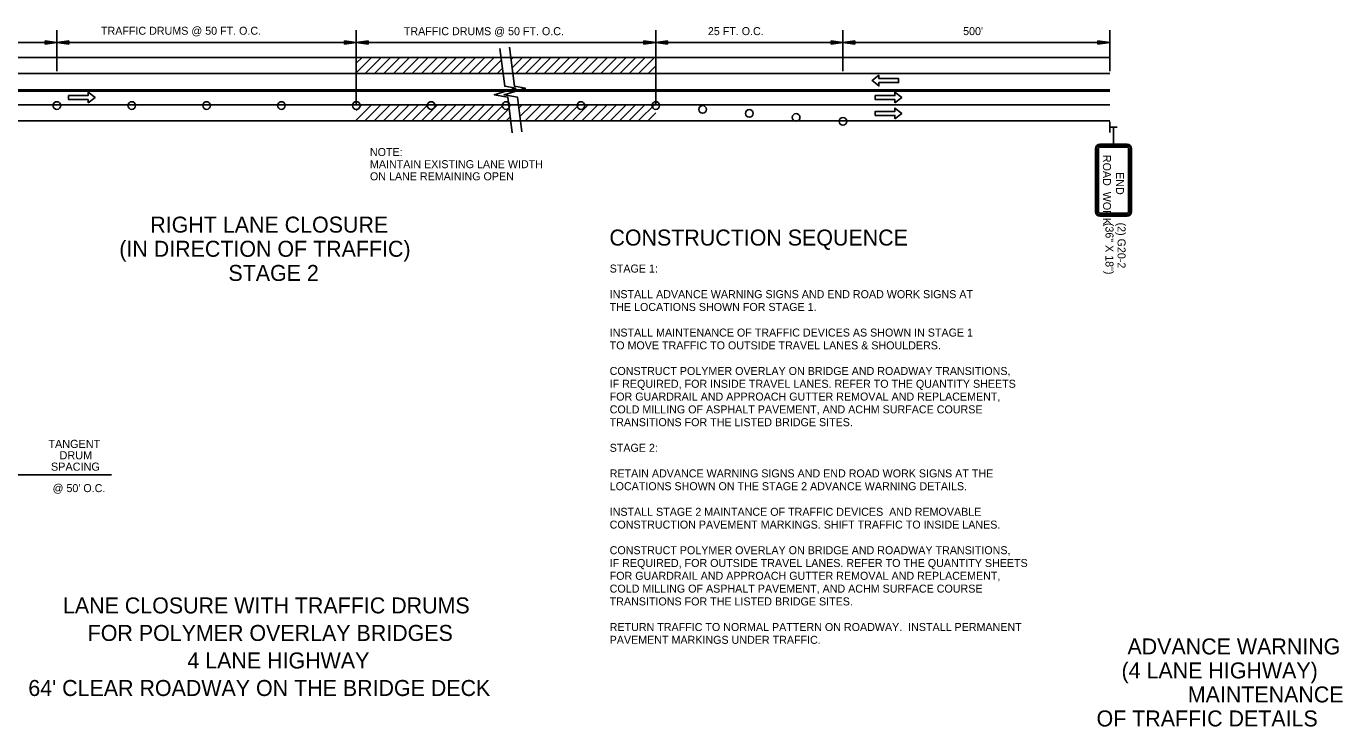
# Model space of a CAD drawing. Extents: x 1930579 to 1937984, y 596452 to 597630.
# Drawn here: x 1936993 to 1937980, y 596607 to 597132 of the extents above; entities that cross this region are included whole.
import ezdxf

# ---------------------------------------------------------------- set-up
doc = ezdxf.new("R2010")
doc.units = 0
for name, color, linetype in [('Default', 7, 'Continuous'), ('P_TC_Signs_Temporary', 7, 'Continuous'), ('R_Annotation', 7, 'Continuous'), ('R_Striping', 7, 'Continuous')]:
    doc.layers.add(name, color=color, linetype=linetype)

msp = doc.modelspace()

# ---------------------------------------------------------------- linework, layer by layer
at = {"layer": 'Default'}
for p, q in [((1937015.53, 597119.89), (1937006.66, 597121.22)), ((1937006.66, 597121.22), (1937006.66, 597118.56)), ((1937015.53, 597129.19), (1937015.53, 597098.47)), ((1937015.53, 597119.89), (1937024.4, 597121.22)), ((1937024.4, 597121.22), (1937024.4, 597118.56)), ((1937231.17, 597118.56), (1937231.17, 597121.22)), ((1937231.17, 597121.22), (1937240.04, 597119.89)), ((1937240.04, 597129.19), (1937240.04, 597073.09)), ((1937248.9, 597121.22), (1937240.04, 597119.89)), ((1937248.9, 597118.56), (1937248.9, 597121.22)), ((1937455.68, 597118.56), (1937455.68, 597121.22)), ((1937455.68, 597121.22), (1937464.54, 597119.89)), ((1937464.54, 597129.19), (1937464.54, 597073.09)), ((1937473.41, 597121.22), (1937464.54, 597119.89)), ((1937473.41, 597118.56), (1937473.41, 597121.22)), ((1937595.99, 597118.56), (1937595.99, 597121.22)), ((1937595.99, 597121.22), (1937604.86, 597119.89)), ((1937604.86, 597129.19), (1937604.86, 597098.47)), ((1937613.73, 597121.22), (1937604.86, 597119.89)), ((1937613.73, 597118.56), (1937613.73, 597121.22)), ((1937795.99, 597118.56), (1937795.99, 597121.22)), ((1937795.99, 597121.22), (1937804.86, 597119.89)), ((1937804.86, 597129.19), (1937804.86, 597098.47)), ((1937015.53, 597119.89), (1936791.02, 597119.89)), ((1937006.66, 597118.56), (1937015.53, 597119.89)), ((1937240.04, 597119.89), (1937015.53, 597119.89)), ((1937024.4, 597118.56), (1937015.53, 597119.89)), ((1937240.04, 597119.89), (1937231.17, 597118.56)), ((1937464.54, 597119.89), (1937240.04, 597119.89)), ((1937240.04, 597119.89), (1937248.9, 597118.56)), ((1937464.54, 597119.89), (1937455.68, 597118.56)), ((1937604.86, 597119.89), (1937464.54, 597119.89)), ((1937464.54, 597119.89), (1937473.41, 597118.56)), ((1937604.86, 597119.89), (1937595.99, 597118.56)), ((1937804.86, 597119.89), (1937604.86, 597119.89)), ((1937604.86, 597119.89), (1937613.73, 597118.56)), ((1937804.86, 597119.89), (1937795.99, 597118.56)), ((1937804.86, 597108.65), (1936452.69, 597108.65)), ((1937240.04, 597097.16), (1937251.53, 597108.65)), ((1937240.04, 597104.23), (1937244.46, 597108.65)), ((1937246.6, 597096.65), (1937258.6, 597108.65)), ((1937253.67, 597096.65), (1937265.67, 597108.65)), ((1937260.74, 597096.65), (1937272.74, 597108.65)), ((1937267.81, 597096.65), (1937279.81, 597108.65)), ((1937274.88, 597096.65), (1937286.88, 597108.65)), ((1937281.95, 597096.65), (1937293.95, 597108.65)), ((1937289.02, 597096.65), (1937301.02, 597108.65)), ((1937296.09, 597096.65), (1937308.09, 597108.65)), ((1937303.17, 597096.65), (1937315.17, 597108.65)), ((1937310.24, 597096.65), (1937322.24, 597108.65)), ((1937317.31, 597096.65), (1937329.31, 597108.65)), ((1937324.38, 597096.65), (1937336.38, 597108.65)), ((1937331.45, 597096.65), (1937343.45, 597108.65)), ((1937338.52, 597096.65), (1937348.79, 597106.92)), ((1937356.05, 597107.11), (1937357.59, 597108.65)), ((1937356.84, 597100.83), (1937364.66, 597108.65)), ((1937359.73, 597096.65), (1937371.73, 597108.65)), ((1937366.81, 597096.65), (1937378.81, 597108.65)), ((1937373.88, 597096.65), (1937385.88, 597108.65)), ((1937380.95, 597096.65), (1937392.95, 597108.65)), ((1937388.02, 597096.65), (1937400.02, 597108.65)), ((1937395.09, 597096.65), (1937407.09, 597108.65)), ((1937402.16, 597096.65), (1937414.16, 597108.65)), ((1937409.23, 597096.65), (1937421.23, 597108.65)), ((1937416.3, 597096.65), (1937428.3, 597108.65)), ((1937423.37, 597096.65), (1937435.37, 597108.65)), ((1937430.45, 597096.65), (1937442.45, 597108.65)), ((1937437.52, 597096.65), (1937449.52, 597108.65)), ((1937444.59, 597096.65), (1937456.59, 597108.65)), ((1937451.66, 597096.65), (1937463.66, 597108.65)), ((1937458.73, 597096.65), (1937464.54, 597102.47)), ((1937804.86, 597096.65), (1936452.69, 597096.65)), ((1937345.59, 597096.65), (1937349.58, 597100.64)), ((1937804.86, 597084.42), (1936452.69, 597084.42)), ((1937804.86, 597083.27), (1936452.69, 597083.27)), ((1937804.86, 597073.09), (1936452.69, 597073.09)), ((1937239.31, 597061.09), (1937251.31, 597073.09)), ((1937240.04, 597068.88), (1937244.24, 597073.09)), ((1937246.39, 597061.09), (1937258.39, 597073.09)), ((1937253.46, 597061.09), (1937265.46, 597073.09)), ((1937260.53, 597061.09), (1937272.53, 597073.09)), ((1937267.6, 597061.09), (1937279.6, 597073.09)), ((1937274.67, 597061.09), (1937286.67, 597073.09)), ((1937281.74, 597061.09), (1937293.74, 597073.09)), ((1937288.81, 597061.09), (1937300.81, 597073.09)), ((1937295.88, 597061.09), (1937307.88, 597073.09)), ((1937302.95, 597061.09), (1937314.95, 597073.09)), ((1937310.03, 597061.09), (1937322.03, 597073.09)), ((1937317.1, 597061.09), (1937329.1, 597073.09)), ((1937324.17, 597061.09), (1937336.17, 597073.09)), ((1937331.24, 597061.09), (1937343.24, 597073.09)), ((1937338.31, 597061.09), (1937350.31, 597073.09)), ((1937350.85, 597080.7), (1937350.89, 597080.74)), ((1937361.97, 597070.61), (1937364.45, 597073.09)), ((1937362.73, 597064.29), (1937371.52, 597073.09)), ((1937366.59, 597061.09), (1937378.59, 597073.09)), ((1937373.67, 597061.09), (1937385.67, 597073.09)), ((1937380.74, 597061.09), (1937392.74, 597073.09)), ((1937387.81, 597061.09), (1937399.81, 597073.09)), ((1937394.88, 597061.09), (1937406.88, 597073.09)), ((1937401.95, 597061.09), (1937413.95, 597073.09)), ((1937409.02, 597061.09), (1937421.02, 597073.09)), ((1937416.09, 597061.09), (1937428.09, 597073.09)), ((1937423.16, 597061.09), (1937435.16, 597073.09)), ((1937430.23, 597061.09), (1937442.23, 597073.09)), ((1937437.3, 597061.09), (1937449.3, 597073.09)), ((1937444.38, 597061.09), (1937456.38, 597073.09)), ((1937451.45, 597061.09), (1937464.54, 597074.18)), ((1937463.45, 597073.09), (1937464.54, 597074.18)), ((1937345.38, 597061.09), (1937354.71, 597070.42)), ((1937352.45, 597061.09), (1937355.47, 597064.1)), ((1937458.52, 597061.09), (1937464.54, 597067.11)), ((1937804.86, 597061.09), (1936452.69, 597061.09)), ((1937804.86, 597052.43), (1937804.86, 597060.41)), ((1937804.98, 597056.4), (1937810.42, 597056.4))]:
    msp.add_line(p, q, dxfattribs=at)
for points in [[(1937347.74, 597115.35), (1937351.28, 597087.03), (1937359.53, 597085.57), (1937343.51, 597080.71), (1937353.71, 597078.77), (1937356.93, 597052)], [(1937354.91, 597116.24), (1937358.56, 597087.03), (1937366.82, 597085.57), (1937350.79, 597080.71), (1937360.99, 597078.77), (1937364.11, 597052.86)]]:
    msp.add_lwpolyline(points, dxfattribs=at)
for centre in [(1937015.53, 597072.6), (1937071.66, 597072.6), (1937127.78, 597072.6), (1937183.91, 597072.6), (1937240.04, 597072.6), (1937296.16, 597072.6), (1937352.29, 597072.6), (1937408.42, 597072.6), (1937464.54, 597072.6), (1937499.62, 597069.63), (1937534.7, 597066.66), (1937569.78, 597063.68), (1937604.86, 597060.71)]:
    msp.add_circle(centre, 2.87, dxfattribs=at)
at = {"layer": 'P_TC_Signs_Temporary'}
for p, q in [((1937817.83, 597043.6), (1937797.58, 597043.6)), ((1937817.83, 597042.66), (1937797.58, 597042.66)), ((1937794.2, 597040.22), (1937794.2, 596992.97)), ((1937795.14, 597040.22), (1937795.14, 596992.97)), ((1937796.45, 597040.22), (1937796.45, 596992.97)), ((1937817.83, 597041.35), (1937797.58, 597041.35)), ((1937818.95, 596992.97), (1937818.95, 597040.22)), ((1937820.26, 596992.97), (1937820.26, 597040.22)), ((1937821.2, 596992.97), (1937821.2, 597040.22)), ((1937797.58, 596991.85), (1937817.83, 596991.85)), ((1937797.58, 596990.54), (1937817.83, 596990.54)), ((1937797.58, 596989.6), (1937817.83, 596989.6))]:
    msp.add_line(p, q, dxfattribs=at)
for centre, radius, start, end in [((1937797.58, 597040.22), 3.38, 90, 180), ((1937797.58, 597040.22), 2.44, 90, 180), ((1937817.83, 597040.22), 3.37, 360, 90), ((1937817.83, 597040.22), 2.44, 360, 90), ((1937797.58, 597040.22), 1.13, 90, 180), ((1937817.83, 597040.22), 1.13, 360, 90), ((1937797.58, 596992.97), 3.37, 180, 270), ((1937797.58, 596992.97), 2.44, 180, 270), ((1937797.58, 596992.97), 1.13, 180, 270), ((1937817.83, 596992.97), 2.44, 270, 360), ((1937817.83, 596992.97), 1.13, 270, 360), ((1937817.83, 596992.97), 3.38, 270, 360)]:
    msp.add_arc(centre, radius, start, end, dxfattribs=at)
at = {"layer": 'R_Annotation'}
for p, q in [((1937807.7, 597056.4), (1937807.7, 597043.6)), ((1936487.9, 596795.58), (1937056.56, 596795.58))]:
    msp.add_line(p, q, dxfattribs=at)
at = {"layer": 'R_Striping'}
for points in [[(1937631.9, 597095.24), (1937626.7, 597091.24), (1937631.9, 597087.24), (1937631.9, 597089.74), (1937646.61, 597089.74), (1937646.61, 597092.74), (1937631.9, 597092.74)], [(1937038.98, 597074.5), (1937044.17, 597078.5), (1937038.98, 597082.5), (1937038.98, 597080), (1937024.27, 597080), (1937024.27, 597077), (1937038.98, 597077)], [(1937643.82, 597074.5), (1937649.01, 597078.5), (1937643.82, 597082.5), (1937643.82, 597080), (1937629.11, 597080), (1937629.11, 597077), (1937643.82, 597077)], [(1937643.82, 597062.73), (1937649.01, 597066.73), (1937643.82, 597070.73), (1937643.82, 597068.23), (1937629.11, 597068.23), (1937629.11, 597065.23), (1937643.82, 597065.23)]]:
    msp.add_lwpolyline(points, close=True, dxfattribs=at)

# ---------------------------------------------------------------- texts
at = {"layer": 'Default'}
for s, height, p in [('TRAFFIC DRUMS @ 50 FT. O.C.', 6, (1937048.61, 597125.66)), ('TRAFFIC DRUMS @ 50 FT. O.C.', 6, (1937275.67, 597125.33)), ('25 FT. O.C.', 6, (1937503.59, 597125.38)), ("500'", 6, (1937694.96, 597125.38)), ('RIGHT LANE CLOSURE', 12, (1937085.58, 596977.28)), ('(IN DIRECTION OF TRAFFIC)', 12, (1937062.33, 596959.17)), ('STAGE 2', 12, (1937144.16, 596941.05)), ('LANE CLOSURE WITH TRAFFIC DRUMS', 12, (1937020.12, 596691.73)), ('FOR POLYMER OVERLAY BRIDGES', 12, (1937038.64, 596671.09)), ('4 LANE HIGHWAY', 12, (1937113.38, 596650.45)), ("64' CLEAR ROADWAY ON THE BRIDGE DECK", 12, (1936994.13, 596629.81))]:
    msp.add_text(s, height=height, rotation=360, dxfattribs=at).set_placement(p)
at = {"layer": 'P_TC_Signs_Temporary'}
for s, p in [('ROAD  WORK', (1937799.83, 597035.56)), ('END', (1937809.58, 597022.63))]:
    msp.add_text(s, height=6, rotation=270, dxfattribs=at).set_placement(p)
at = {"layer": 'R_Annotation'}
for s, height, rotation, p in [('NOTE:', 6, 360, (1937250.26, 597034.72)), ('ON LANE REMAINING OPEN', 6, 360, (1937250.26, 597016.5)), ('MAINTAIN EXISTING LANE WIDTH', 6, 360, (1937250.26, 597025.61)), ('(36" X 18")', 6, 270, (1937801.7, 596984.6)), ('(2) G20-2', 6, 270, (1937810.76, 596984.81)), ('CONSTRUCTION SEQUENCE', 12, 360, (1937429.8, 596967.58)), ('STAGE 1:', 6, 360, (1937429.99, 596947.33)), ('INSTALL ADVANCE WARNING SIGNS AND END ROAD WORK SIGNS AT', 6, 360, (1937429.99, 596928.13)), ('THE LOCATIONS SHOWN FOR STAGE 1.', 6, 360, (1937429.99, 596918.53)), ('INSTALL MAINTENANCE OF TRAFFIC DEVICES AS SHOWN IN STAGE 1', 6, 360, (1937429.99, 596899.33)), ('TO MOVE TRAFFIC TO OUTSIDE TRAVEL LANES & SHOULDERS.', 6, 360, (1937429.99, 596889.73)), ('CONSTRUCT POLYMER OVERLAY ON BRIDGE AND ROADWAY TRANSITIONS,', 6, 360, (1937429.99, 596870.53)), ('IF REQUIRED, FOR INSIDE TRAVEL LANES. REFER TO THE QUANTITY SHEETS ', 6, 360, (1937429.99, 596860.93)), ('FOR GUARDRAIL AND APPROACH GUTTER REMOVAL AND REPLACEMENT, ', 6, 360, (1937429.99, 596851.33)), ('COLD MILLING OF ASPHALT PAVEMENT, AND ACHM SURFACE COURSE ', 6, 360, (1937429.99, 596841.73)), ('TRANSITIONS FOR THE LISTED BRIDGE SITES.', 6, 360, (1937429.99, 596832.13)), ('TANGENT', 6.094, 360, (1937009.17, 596815.8)), ('STAGE 2:', 6, 360, (1937429.99, 596812.93)), ('DRUM', 6.094, 360, (1937017.54, 596807.27)), ('SPACING', 6.094, 360, (1937011.09, 596798.74)), ('RETAIN ADVANCE WARNING SIGNS AND END ROAD WORK SIGNS AT THE', 6, 360, (1937429.99, 596793.73)), ("@ 50' O.C.", 6, 360, (1937012.34, 596782.7)), ('LOCATIONS SHOWN ON THE STAGE 2 ADVANCE WARNING DETAILS.', 6, 360, (1937429.99, 596784.13)), ('INSTALL STAGE 2 MAINTANCE OF TRAFFIC DEVICES  AND REMOVABLE', 6, 360, (1937429.99, 596764.93)), ('CONSTRUCTION PAVEMENT MARKINGS. SHIFT TRAFFIC TO INSIDE LANES.', 6, 360, (1937429.99, 596755.33)), ('CONSTRUCT POLYMER OVERLAY ON BRIDGE AND ROADWAY TRANSITIONS,', 6, 360, (1937429.99, 596736.13)), ('IF REQUIRED, FOR OUTSIDE TRAVEL LANES. REFER TO THE QUANTITY SHEETS ', 6, 360, (1937429.99, 596726.53)), ('FOR GUARDRAIL AND APPROACH GUTTER REMOVAL AND REPLACEMENT, ', 6, 360, (1937429.99, 596716.93)), ('COLD MILLING OF ASPHALT PAVEMENT, AND ACHM SURFACE COURSE ', 6, 360, (1937429.99, 596707.33)), ('TRANSITIONS FOR THE LISTED BRIDGE SITES.', 6, 360, (1937429.99, 596697.73)), ('RETURN TRAFFIC TO NORMAL PATTERN ON ROADWAY.  INSTALL PERMANENT', 6, 360, (1937429.99, 596678.53)), ('PAVEMENT MARKINGS UNDER TRAFFIC.', 6, 360, (1937429.99, 596668.93)), ('ADVANCE WARNING', 12, 360, (1937818.16, 596660.97)), (' (4 LANE HIGHWAY)', 12, 360, (1937809.28, 596642.97)), ('MAINTENANCE ', 12, 360, (1937863.42, 596624.97)), ('OF TRAFFIC DETAILS', 12, 360, (1937795.01, 596606.97))]:
    msp.add_text(s, height=height, rotation=rotation, dxfattribs=at).set_placement(p)

doc.saveas('drawing.dxf')
